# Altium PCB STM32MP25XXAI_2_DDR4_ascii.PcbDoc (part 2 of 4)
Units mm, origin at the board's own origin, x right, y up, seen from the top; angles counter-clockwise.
Board outline 172 x 137 mm, 4 copper layers (Top Layer, Signal Layer 1, Signal Layer 2, Bottom Layer), stack 1.614 mm thick; 241 components, 153 nets, 1312 pads, 924 vias.
Unrouted connection lines stored in the file: 13.
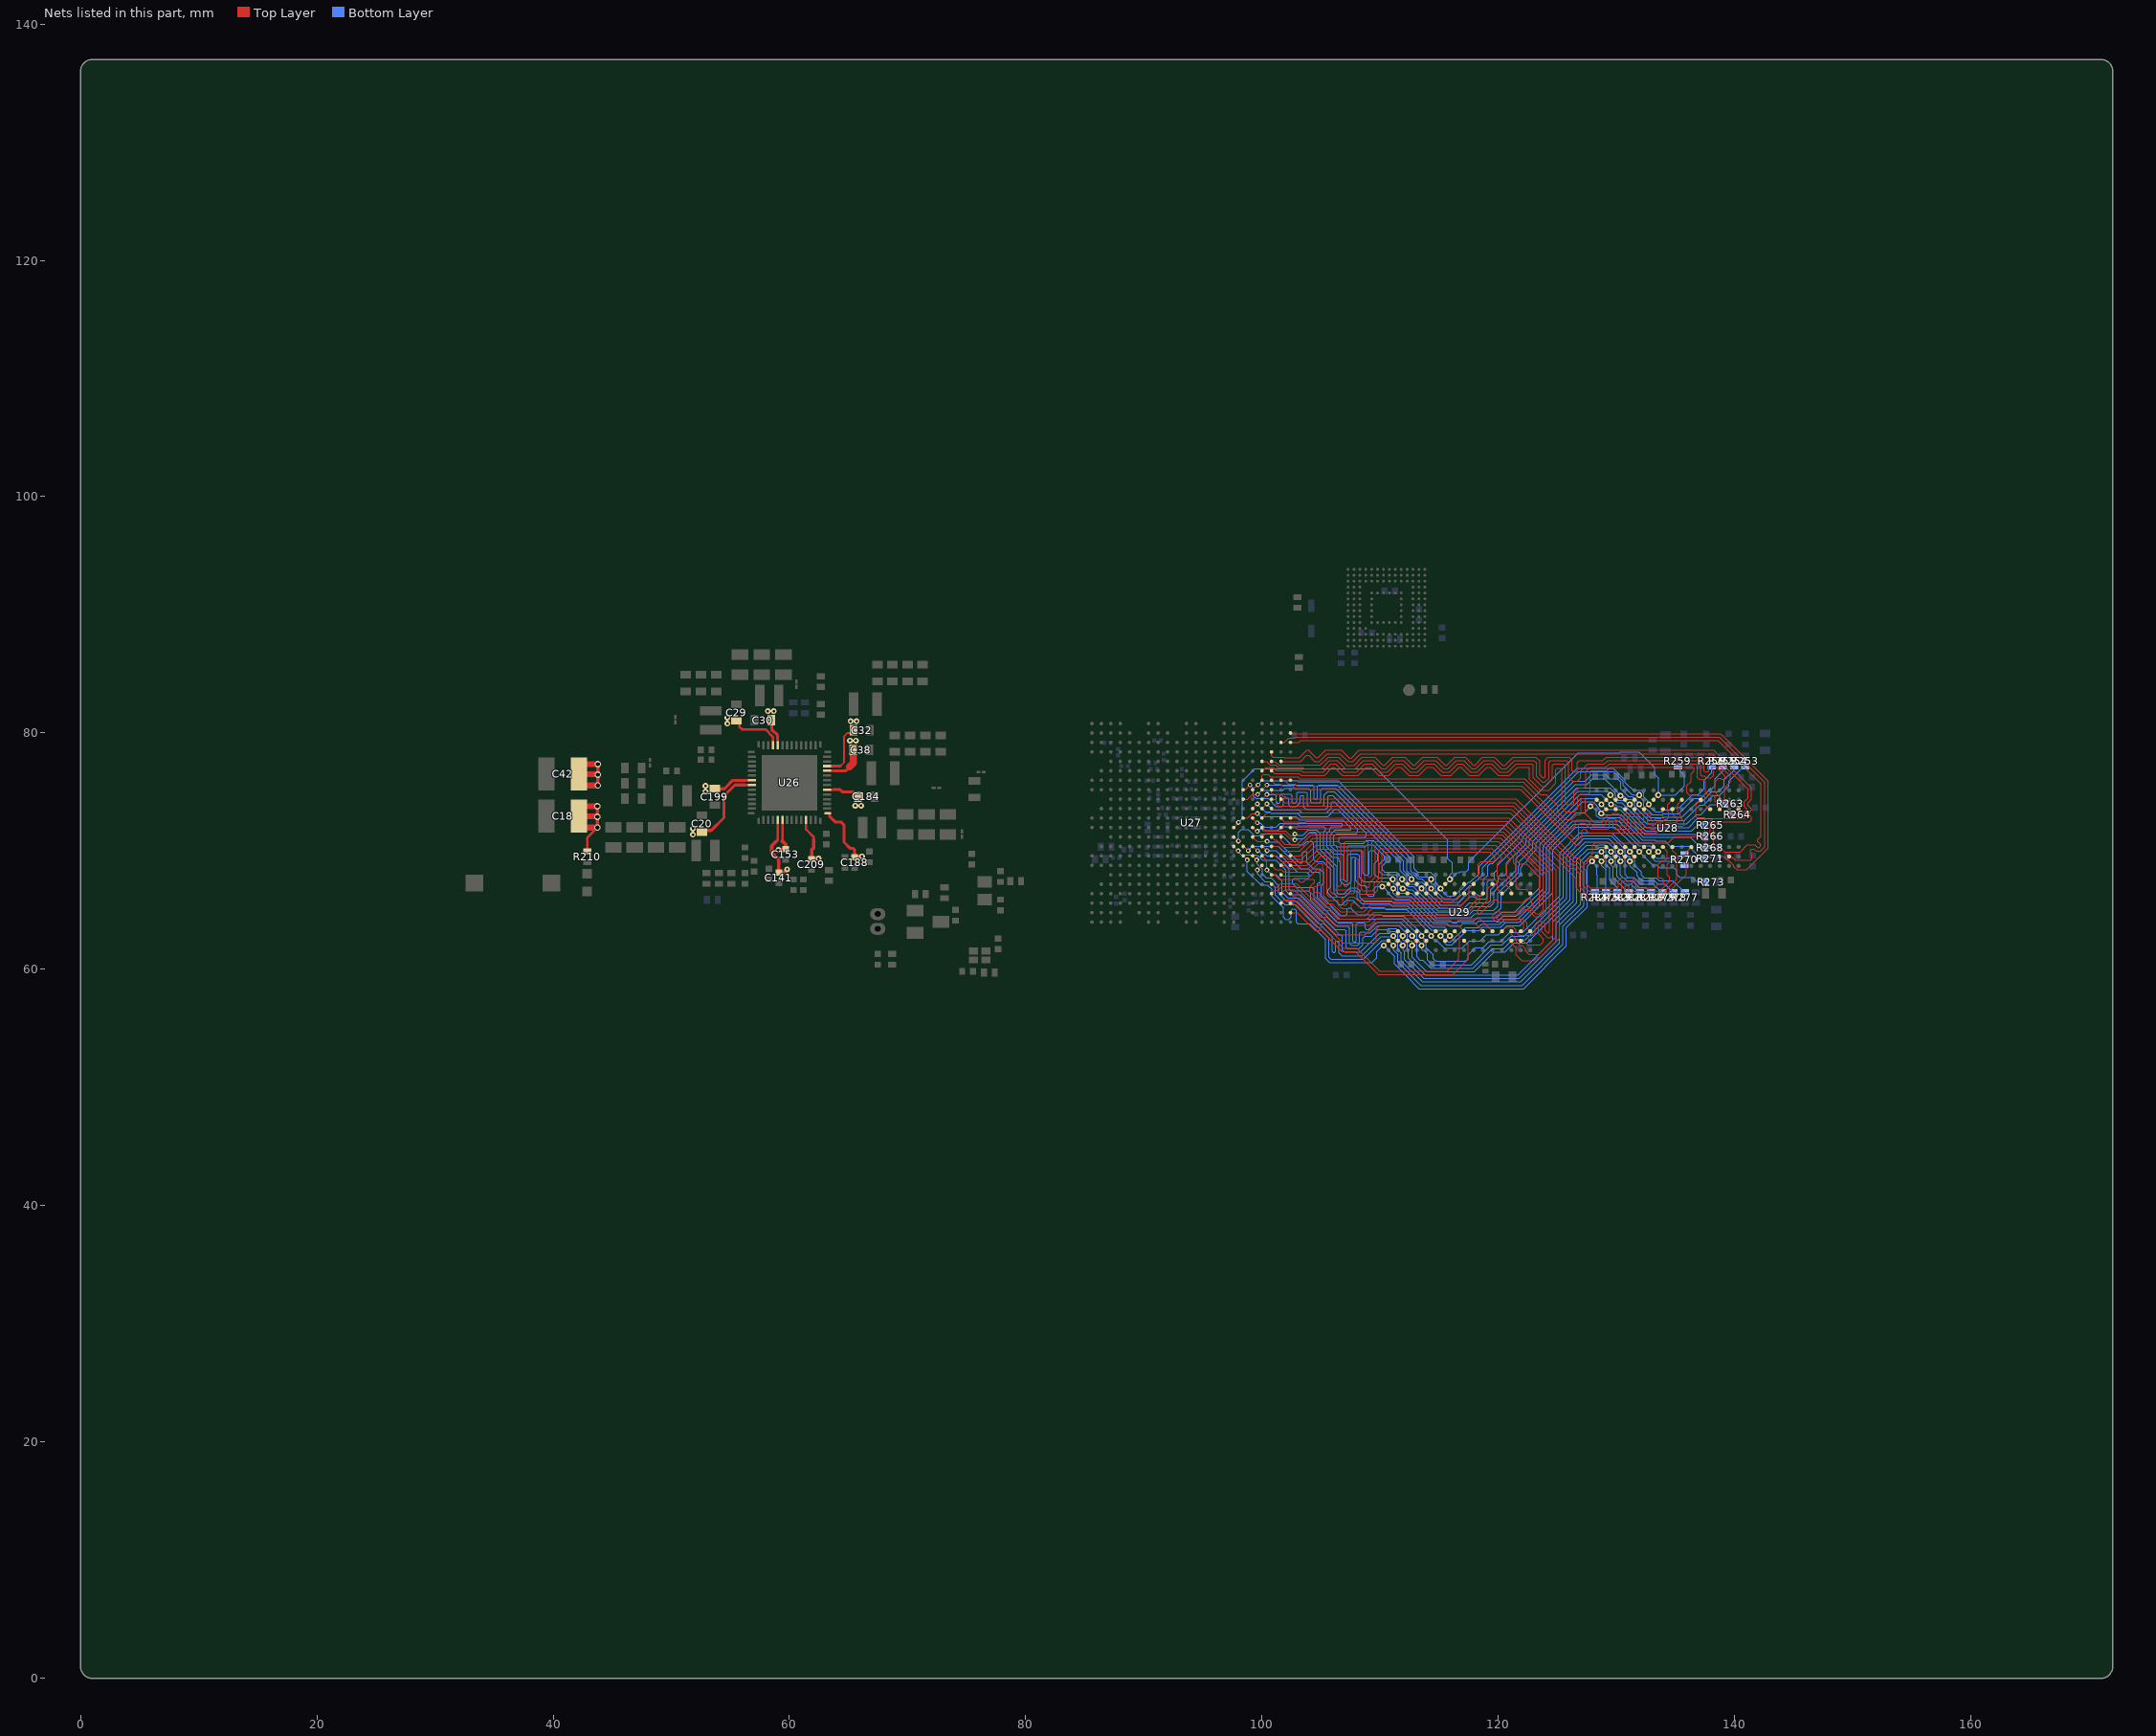
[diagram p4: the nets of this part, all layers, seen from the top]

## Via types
v1: diameter 0.55, hole 0.35, Top Layer to Bottom Layer, 432 vias
v2: diameter 0.4, hole 0.2, Top Layer to Bottom Layer, tented both sides, 202 vias
v3: diameter 0.5, hole 0.2, Top Layer to Bottom Layer, 146 vias
v4: diameter 0.5, hole 0.25, Top Layer to Bottom Layer, 144 vias

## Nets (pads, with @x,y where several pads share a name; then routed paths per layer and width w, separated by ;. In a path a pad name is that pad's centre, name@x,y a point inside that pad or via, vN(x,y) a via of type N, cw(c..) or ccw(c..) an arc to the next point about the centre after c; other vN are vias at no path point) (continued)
5V_STLK: C18.1 C20.2 C29.2 C30.2 C32.2 C38.2 C42.1 C153.2 C184.2 C188.2 C199.2 C209.2 R210.1 U26.6 U26.11 U26.15 U26.20 U26.24 U26.25 U26.38 U26.39 U26.49 U26.50 | length 56.5
  Top Layer w0.15: 64.3,77.2 64.625,77.525 64.625,79.731 64.888,79.994 65.319,79.994 C32.2@65.425,80.1
  Top Layer w0.2: R210.1@42.887,69.97 42.887,71.138 v1(43.751,72.002)
  Top Layer w0.21: C29.2@55.525,81.05 55.762,80.813 55.762,80.513 55.975,80.3 57.964,80.3 58.6,79.664 U26.39@58.6,78.97 ; 56.275,75.6 U26.50@56.83,75.6 ; 56.275,76 U26.49@56.83,76 ; U26.38@59,78.97 59,79.525 ; 59.4,70.85 U26.6@59.4,72.63 ; U26.11@61.4,72.63 61.4,71.843 62.04,71.203 62.04,70.975 ; U26.15@63.17,73.2 U26.15@63.245,73.2 U26.15@63.285,73.2 ; U26.20@63.17,75.2 63.725,75.2 ; U26.24@63.17,76.8 63.725,76.8 ; U26.25@63.17,77.2 64.3,77.2
  Top Layer w0.25: C20.2@52.6,71.75 53.375,71.75 54.45,72.825 54.45,74.669 55.381,75.6 56.275,75.6 ; C199.2@53.675,75.275 54.491,75.275 55.216,76 56.275,76 ; C30.2@58.425,81.075 58.494,81.006 58.494,80.308 59,79.802 59,79.525 ; 63.395,73.095 63.395,72.947 63.871,72.472 64.353,72.472 64.625,72.2 64.625,70.759 65.134,70.25 65.379,70.25 65.525,70.104 C188.2@65.525,69.55 ; 63.725,75.2 64.288,75.2 64.463,75.025 65.347,75.025 65.472,74.9 65.55,74.9 65.747,74.703 C184.2@65.747,74.625 ; 63.725,76.8 64.75,76.8 65.075,77.125
  Top Layer w0.3: v1(43.751,72.002) v1(43.751,72.902) v1(43.751,73.802) ; v1(43.776,75.565) v1(43.776,76.465) v1(43.776,77.365) ; v3(59.065,70.11) 59.675,70.11 59.674,70.111 59.674,70.576 59.4,70.85 ; C209.2@61.85,69.38 C209.2@61.875,69.38 ; 62.04,70.975 62.04,70.269 61.875,70.104 C209.2@61.875,69.38 ; v3(62.46,69.38) C209.2@61.875,69.38 ; C188.2@65.525,69.55 v3(66.135,69.55)
  Top Layer w0.5: C18.1@42.187,72.049 42.235,72.002 v1(43.751,72.002) ; C18.1@42.187,72.961 43.679,72.961 43.737,72.902 v1(43.751,72.902) ; C42.1@42.187,75.612 42.235,75.565 v1(43.776,75.565) ; C42.1@42.187,76.523 43.704,76.523 43.762,76.465 v1(43.776,76.465) ; C18.1@42.246,73.802 v1(43.751,73.802) ; C42.1@42.246,77.365 v1(43.776,77.365)
  Top Layer w0.6: 65.075,77.125 65.4,77.45 C38.2@65.4,78.175
  other v3: 51.825,71.4 51.825,71.9 65.575,73.85 66.075,73.85 52.9,75.025 52.9,75.525 65.125,79.35 65.625,79.35 54.75,80.8 65.175,81 65.675,81 54.75,81.3 58.175,81.85 58.675,81.85
5V_VCONN: C141.1 U26.5 | length 5.7
  Top Layer w0.21: 58.877,70.828 59,70.95 U26.5@59,72.63
  Top Layer w0.3: 58.877,70.828 58.51,70.46 58.51,69.865 59.1,69.275 C141.1@59.1,68.2 59.539,68.2 v3(59.8,68.46)
DDR_A0: R265.1 U27.K18 U28.P3 U29.P3 | length 57.5
  Top Layer w0.09: U27.K18@99.2,73.6 v2(99.6,74) ; v4(111.9,66.825) 111.941,66.825 112.294,66.472 U29.P3@112.294,66.422 ; v4@129.532,73.928 129.572,73.928 129.925,73.575 U28.P3@129.925,73.55 U28.P3@129.925,73.525
  Bottom Layer w0.09: v2(99.6,74) 100.267,73.333 100.646,73.333 100.771,73.209 102.988,73.209 103.252,72.945 105.581,72.945 106.158,73.522 106.2,73.522 106.384,73.522 108.091,71.815 108.091,71.615 107.965,71.49 106.3,71.49 106.077,71.267 106.077,70.58 106.3,70.357 108.748,70.357 ; 108.748,70.359 108.914,70.526 109.38,70.526 110.359,69.547 110.359,69.324 109.909,68.874 109.909,68.291 110.177,68.022 111.269,68.022 111.449,67.842 111.449,67.352 111.894,66.908 v4@111.938,66.863 ; v4(111.9,66.825) 111.938,66.862 112.233,66.862 112.365,66.73 112.708,66.73 114.805,64.633 117.533,64.633 117.9,65 119.589,65 119.939,65.349 119.939,66.445 121.7,68.206 121.7,68.718 121.76,68.779 121.76,69.109 122.92,70.269 122.92,70.811 126.885,74.775 128.71,74.775 129.525,73.959 v4(129.525,73.95) ; v4@129.551,73.95 129.885,73.95 130.04,73.795 130.363,73.795 132.433,71.725 136.35,71.725 136.825,72.2 R265.1@137.5,72.2
DDR_A1: R281.1 U27.P16 U28.P7 U29.P7 | length 54.7
  Top Layer w0.09: U27.P16@97.6,70.4 v2(97.975,70.025) ; v4(111.9,62.825) U29.P7@112.3,63.225 ; v4@129.54,69.936 U28.P7@129.932,70.328
  Bottom Layer w0.09: v2(97.975,70.025) 97.975,69.95 98.25,69.675 99.45,69.675 99.53,69.595 99.693,69.595 100.029,69.259 101.146,69.259 101.995,68.41 101.995,66.636 102.285,66.347 103.212,66.347 106.181,63.378 106.972,63.378 107.099,63.25 107.099,61.878 107.235,61.742 108.219,61.742 108.555,62.078 108.555,62.657 108.702,62.804 109.281,62.804 109.834,63.357 110.575,63.357 110.675,63.457 111.319,63.457 111.37,63.405 111.9,62.875 v4(111.9,62.825) ; v4@111.9,62.816 111.9,62.504 111.985,62.42 112.064,62.42 112.295,62.189 112.295,61.694 112.365,61.624 112.365,60.958 113.803,59.52 121.655,59.52 124.605,62.47 124.605,64 126.361,65.756 126.361,69.387 127.456,70.482 128.43,70.482 128.483,70.535 129.004,70.535 129.525,70.014 v4(129.525,69.95) 129.525,69.9 129.725,69.7 129.725,69.509 129.92,69.314 129.92,68.88 130.035,68.765 130.035,67.886 130.722,67.2 131.225,67.2 131.9,66.525 R281.1@131.975,66.525
DDR_A2: R268.1 U27.L18 U28.R3 U29.R3 | length 60.6
  Top Layer w0.09: U27.L18@99.2,72.8 v2(99.6,72.4) ; v4(111.1,66.825) 111.141,66.825 111.494,66.472 U29.R3@111.494,66.422 ; v4(128.703,73.185) 128.781,73.263 128.781,73.381 128.908,73.508 129.084,73.508 U28.R3@129.125,73.55
  Bottom Layer w0.09: v2(99.6,72.4) 99.622,72.378 99.872,72.378 100.195,72.055 101.218,72.055 101.528,72.365 106.721,72.365 106.794,72.291 106.794,72.149 106.716,72.07 105.894,72.07 105.758,71.934 105.758,71.768 105.497,71.508 105.497,70.339 106.06,69.777 106.75,69.777 106.925,69.602 106.925,67.578 107.028,67.475 107.168,67.475 107.254,67.56 107.254,69.636 107.395,69.777 108.048,69.777 108.235,69.59 108.235,67.779 108.578,67.437 110.489,67.437 v4(111.1,66.825) 111.103,66.823 111.103,66.466 111.409,66.16 112.571,66.16 114.598,64.133 115.925,64.133 ; 115.925,64.132 116.116,63.94 116.457,63.94 116.65,64.133 117.958,64.133 118.21,64.385 ; 118.212,64.385 118.227,64.401 119.865,64.401 120.277,64.813 121.373,64.813 123.5,66.94 123.5,70.57 127.125,74.195 127.964,74.195 128.055,74.104 128.277,73.882 128.277,73.84 128.635,73.482 128.635,73.253 v4(128.703,73.185) 128.778,73.109 130.37,73.109 132.282,71.197 ; 132.28,71.195 136.23,71.195 137.125,70.3 R268.1@137.5,70.3
DDR_A3: R279.1 U27.P19 U28.N7 U29.N7 | length 57
  Top Layer w0.09: U27.P19@100,70.4 100.038,70.4 100.388,70.05 v2(100.425,70.05) ; v4(112.7,62.825) 112.724,62.825 113.094,63.195 U29.N7@113.094,63.222 ; v4@130.355,69.928 130.725,70.298 U28.N7@130.725,70.325
  Bottom Layer w0.09: v2(100.425,70.05) 101.175,70.05 102.992,68.234 103.762,68.234 103.993,68.003 103.993,67.765 103.94,67.713 102.738,67.713 102.575,67.55 102.575,67.25 102.898,66.927 104.298,66.927 104.415,66.81 104.415,65.963 106.421,63.958 107.549,63.958 107.679,63.828 107.679,62.403 107.759,62.322 107.922,62.322 107.975,62.375 107.975,63.81 108.123,63.958 108.606,63.958 108.725,63.839 108.725,63.481 108.822,63.384 109.037,63.384 109.631,63.978 111.711,63.978 112.661,63.028 112.661,62.864 v4(112.7,62.825) 112.7,62.775 112.9,62.575 112.9,62.384 113.104,62.18 113.104,61.046 113.37,60.78 113.595,60.78 114.275,60.1 117.854,60.1 119.521,61.767 120.455,61.767 121.221,62.533 122.318,62.533 125.781,65.997 125.781,69.627 127.204,71.05 129.338,71.05 130.17,70.217 130.17,70.208 130.325,70.053 130.325,69.9 130.513,69.713 130.513,69.588 130.6,69.5 130.6,69.434 130.72,69.314 130.72,68.021 130.939,67.803 131.443,67.803 132.021,67.225 133.086,67.225 133.376,66.935 133.389,66.935 133.39,66.934 133.417,66.934 133.825,66.525 R279.1@133.875,66.525
  other v4: 130.325,69.95
DDR_A4: R263.1 U27.H17 U28.N3 U29.N3 | length 59.9
  Top Layer w0.09: U27.H17@98.4,75.2 98.419,75.219 98.604,75.219 v2@98.98,75.595 ; U29.N3@113.094,66.422 113.094,66.47 113.449,66.825 v4@113.5,66.825 ; U28.N3@130.725,73.525 130.725,73.573 131.102,73.95 v4(131.125,73.95)
  Bottom Layer w0.09: v2(98.98,75.6) 99.255,75.325 99.255,74.682 99.484,74.453 100.517,74.453 101.181,73.789 101.696,73.789 101.829,73.922 101.829,74.427 101.924,74.522 102.164,74.522 102.256,74.429 102.256,73.922 102.389,73.789 102.904,73.789 103.221,74.105 103.221,74.641 103.3,74.72 103.458,74.72 103.528,74.65 103.528,73.747 103.751,73.525 105.341,73.525 105.563,73.747 105.563,74.638 105.65,74.725 106.001,74.725 111.695,69.031 111.695,68.342 112.251,67.787 112.251,67.397 112.438,67.21 112.85,67.21 113.002,67.059 113.267,67.059 113.5,66.825 113.5,66.718 113.498,66.715 115.031,65.182 117.108,65.182 117.55,65.625 119.139,65.625 119.359,65.844 119.359,66.748 120.012,67.402 120.012,67.833 120.125,67.945 120.508,67.945 120.695,68.133 120.695,68.98 122.34,70.625 122.34,71.051 126.645,75.355 129.429,75.355 129.87,74.914 129.87,74.756 129.925,74.701 129.925,74.541 130.161,74.305 130.651,74.305 131.006,73.95 v4(131.125,73.95) 131.125,73.825 131.395,73.555 131.395,73.47 132.56,72.305 135.952,72.305 136.748,73.101 137.126,73.101 137.95,73.925 R263.1@139.2,73.925
  other v4: 113.5,66.85
DDR_A5: R282.1 U27.R19 U28.P8 U29.P8 | length 50.8
  Top Layer w0.09: U27.R19@100,69.6 100.4,69.2 v2(100.4,68.4) ; v4(111.9,62.025) 111.9,62.055 U29.P8@112.269,62.424 ; v4@129.532,69.158 U28.P8@129.901,69.527
  Bottom Layer w0.09: v2(100.4,68.4) 100.785,68.015 101.15,68.015 101.705,67.46 101.705,66.516 102.165,66.057 103.092,66.057 106.228,62.92 106.686,62.92 106.809,62.797 106.809,61.639 106.996,61.452 108.339,61.452 109.954,63.067 110.784,63.067 110.937,63.22 111.264,63.22 111.495,62.989 111.495,62.545 111.9,62.14 v4(111.9,62.025) 111.939,61.986 111.939,61.64 112.075,61.504 112.075,60.838 113.683,59.23 121.775,59.23 124.895,62.35 124.895,63.88 126.651,65.636 126.651,69.267 127.574,70.189 128.406,70.189 128.562,70.345 128.889,70.345 129.12,70.114 129.12,69.8 129.13,69.79 129.13,69.786 129.362,69.555 129.431,69.555 129.5,69.485 129.5,69.175 v4(129.525,69.15) 129.525,68.85 129.7,68.675 129.7,67.775 130.95,66.525 R282.1@131.025,66.525
DDR_A6: R264.1 U27.K19 U28.P2 U29.P2 | length 60.3
  Top Layer w0.09: U27.K19@100,73.6 v2(100.4,74) ; v4@111.9,67.6 111.916,67.6 112.283,67.233 U29.P2@112.308,67.233 ; v4(129.475,74.75) 129.5,74.75 129.9,74.35 U28.P2@129.925,74.35
  Bottom Layer w0.09: v2(100.4,74) 100.4,73.99 100.891,73.499 103.108,73.499 103.372,73.235 105.461,73.235 105.853,73.627 105.853,74.078 105.975,74.2 106.116,74.2 108.8,71.516 108.8,71.292 108.708,71.2 106.6,71.2 106.5,71.1 106.5,70.747 106.6,70.647 108.578,70.647 108.814,70.883 109.433,70.883 109.803,70.513 110.894,69.422 110.894,69.208 110.773,69.087 110.532,69.087 110.199,68.754 110.199,68.412 110.225,68.385 110.361,68.25 111.315,68.25 111.9,67.664 111.9,67.489 112.022,67.368 112.022,67.357 112.359,67.02 112.772,67.02 114.86,64.932 117.283,64.932 117.675,65.325 119.326,65.325 119.649,65.648 119.649,66.565 121.495,68.411 121.495,69.37 122.63,70.505 122.63,70.931 126.765,75.065 129.21,75.065 v4@129.5,74.775 ; v4(129.475,74.75) 129.745,74.48 129.745,74.37 130.03,74.085 130.432,74.085 132.502,72.015 136.126,72.015 136.861,72.75 139.327,72.75 139.431,72.855 139.59,72.855 139.8,73.065 R264.1@139.8,73.075
  other v4: 111.85,67.625
DDR_A7: R275.1 U27.T19 U28.R8 U29.R8 | length 48.8
  Top Layer w0.09: v2(99.6,68.4) U27.T19@100,68.8 ; v4(111.1,62.025) U29.R8@111.5,62.425 ; v4@128.732,69.128 U28.R8@129.132,69.528
  Bottom Layer w0.09: v2(99.6,68.4) 99.607,68.393 99.607,68.059 100.231,67.435 100.628,67.435 101.125,66.938 101.125,66.276 101.924,65.477 102.823,65.477 105.649,62.65 105.649,61.035 105.812,60.872 108.587,60.872 ; 108.587,60.873 110.132,62.417 110.134,62.417 110.137,62.42 110.705,62.42 v4(111.1,62.025) ; v4@111.107,62.025 111.126,62.006 111.126,61.633 111.495,61.264 111.495,60.598 113.443,58.65 122.015,58.65 125.475,62.11 125.475,63.64 127.231,65.396 127.231,69.026 127.75,69.545 128.337,69.545 v4@128.725,69.157 ; v4@128.732,69.15 128.757,69.125 128.757,68.776 129.12,68.413 R275.1@129.12,66.53
  other v4: 128.725,69.15
DDR_A8: R266.1 U27.L17 U28.R2 U29.R2 | length 60.5
  Top Layer w0.09: U27.L17@98.4,72.8 98.783,72.8 99.158,73.175 v2(99.6,73.175) ; v4@111.094,67.622 U29.R2@111.494,67.222 ; v4(128.725,73.95) U28.R2@129.125,74.35
  Bottom Layer w0.09: v2(99.6,73.175) 99.856,72.919 102.868,72.919 103.132,72.655 106.841,72.655 107.525,71.971 107.525,71.833 107.473,71.78 106.18,71.78 105.787,71.388 105.787,70.46 106.18,70.067 108.458,70.067 108.525,70 108.525,68.156 108.694,67.988 108.975,67.988 109.075,68.088 109.075,69.967 109.175,70.067 109.429,70.067 109.805,69.691 109.805,69.23 109.519,68.944 109.519,68.027 109.814,67.732 v4@110.873,67.732 ; v4@111.14,67.576 111.14,67.293 111.213,67.22 111.264,67.22 111.5,66.984 111.5,66.525 111.595,66.43 112.655,66.43 114.702,64.383 117.693,64.383 118.001,64.691 119.716,64.691 120.229,65.203 120.229,66.303 121.905,67.98 121.905,68.589 122.038,68.721 122.038,68.788 122.55,69.3 122.55,69.465 123.21,70.125 123.21,70.69 126.797,74.277 127.005,74.485 128.201,74.485 128.725,73.961 v4(128.725,73.95) 129.12,73.555 130.263,73.555 132.372,71.446 136.654,71.446 136.85,71.25 R266.1@137.5,71.25
  other v4: 111.05,67.625
DDR_A9: R283.1 U27.R18 U28.R7 U29.R7 | length 52.1
  Top Layer w0.09: U27.R18@99.2,69.6 v2(99.55,69.25) ; v4(111.1,62.825) 111.494,63.218 U29.R7@111.494,63.222 ; v4@128.732,69.928 129.125,70.321 U28.R7@129.125,70.325
  Bottom Layer w0.09: v2(99.55,69.25) 99.595,69.205 99.595,68.9 100.026,68.47 100.026,68.05 100.346,67.73 100.66,67.73 100.665,67.725 100.749,67.725 101.415,67.058 101.415,66.396 102.044,65.767 102.943,65.767 105.939,62.77 105.939,61.528 106.021,61.446 106.135,61.446 106.229,61.54 106.229,62.327 106.282,62.379 106.451,62.379 106.519,62.311 106.519,61.381 106.738,61.162 108.459,61.162 110.074,62.777 111.052,62.777 v4(111.1,62.825) 111.1,62.726 111.303,62.523 111.303,62.415 111.5,62.218 111.5,61.669 111.785,61.384 111.785,60.718 113.563,58.94 121.895,58.94 125.185,62.23 125.185,63.76 126.941,65.516 126.941,69.146 127.694,69.899 128.674,69.899 v4(128.725,69.95) ; v4@128.725,69.925 128.725,69.867 128.9,69.692 128.9,69.534 129.12,69.314 129.12,68.83 129.41,68.54 129.41,67.562 130.075,66.897 R283.1@130.075,66.525
DDR_A10: R254.1 U27.J17 U28.M3 U29.M3 | length 60
  Top Layer w0.09: U27.J17@98.4,74.4 98.783,74.4 99.183,74.8 v2(99.625,74.8) ; U29.M3@113.894,66.422 113.894,66.47 114.249,66.825 v4(114.3,66.825) ; U28.M3@131.525,73.55 131.525,73.573 v4@131.88,73.928
  Bottom Layer w0.09: v2(99.625,74.8) 99.632,74.8 99.977,75.145 101.792,75.145 101.948,75.3 103.933,75.3 104.108,75.125 104.108,74.2 104.204,74.105 104.886,74.105 104.983,74.203 104.983,75.2 105.088,75.305 106.242,75.305 112.275,69.271 112.275,68.325 112.58,68.02 112.814,68.02 113.187,67.647 113.531,67.647 114.091,67.087 114.091,67.083 114.3,66.873 v4(114.3,66.825) v4@114.3,66.717 ; v4@114.298,66.715 115.331,65.682 116.653,65.682 117.549,66.578 117.95,66.578 118.285,66.242 118.651,66.242 118.755,66.347 118.755,67.616 119.1,67.961 119.1,68.745 119.325,68.97 119.509,68.97 121.76,71.221 121.76,71.291 126.404,75.935 127.368,75.935 127.868,76.435 129.115,76.435 129.438,76.112 130.095,76.112 130.36,75.847 130.36,75.268 131.015,74.613 131.337,74.613 131.925,74.025 v4(131.925,73.95) 131.925,73.836 132.22,73.541 132.22,73.466 132.851,72.835 133.987,72.835 134.037,72.885 135.554,72.885 136.864,74.195 137.255,74.195 138.075,75.015 138.599,75.015 139.12,75.536 139.12,76.034 139.95,76.864 R254.1@139.95,77.175
DDR_A11: R271.1 U27.M18 U28.T2 U29.T2 | length 59.8
  Top Layer w0.09: U27.M18@99.2,72 99.237,72 99.562,71.675 v2(99.6,71.675) ; v4(110.175,67) 110.423,67 110.647,67.224 U29.T2@110.694,67.224 ; v4@127.797,73.798 U28.T2@128.326,74.327
  Bottom Layer w0.09: v2(99.6,71.675) 99.6,71.677 99.79,71.867 99.973,71.867 100.089,71.751 101.324,71.751 101.648,72.075 105.226,72.075 105.375,71.925 105.375,71.796 105.207,71.628 105.207,70.219 105.94,69.487 106.405,69.487 106.52,69.372 106.52,69.168 106.635,69.053 106.635,67.458 106.908,67.185 107.288,67.185 107.579,67.475 107.579,69.402 107.664,69.487 107.858,69.487 107.945,69.4 107.945,67.505 108.35,67.1 108.75,67.1 108.855,66.995 108.855,66.376 109.015,66.215 109.412,66.215 109.519,66.322 109.519,66.856 109.662,67 v4(110.175,67) 110.216,67 110.625,66.59 110.625,66.507 111.242,65.89 112.488,65.89 114.495,63.883 115.625,63.883 115.858,63.65 116.782,63.65 117.015,63.883 118.118,63.883 118.33,64.095 ; 118.332,64.095 118.347,64.111 119.985,64.111 120.397,64.523 121.493,64.523 123.79,66.82 123.79,70.45 126.59,73.25 127.266,73.25 127.8,73.784 v4(127.8,73.8) 127.907,73.8 128.301,73.406 128.301,73.028 128.539,72.79 128.866,72.79 128.919,72.842 130.297,72.842 132.18,70.959 133.217,70.959 133.327,70.85 134.1,70.85 134.545,70.405 136.12,70.405 137.175,69.35 R271.1@137.5,69.35
DDR_A12: R277.1 U27.N18 U28.M7 U29.M7 | length 56.3
  Top Layer w0.09: U27.N18@99.2,71.2 99.575,70.825 v2(100.425,70.825) ; v4(113.5,62.825) 113.524,62.825 113.894,63.195 U29.M7@113.894,63.222 ; v4@131.132,69.928 131.155,69.928 131.525,70.298 U28.M7@131.525,70.325
  Bottom Layer w0.09: v2(100.425,70.825) 100.45,70.8 101.386,70.8 103.202,68.984 103.334,68.984 103.438,69.087 103.438,69.885 103.525,69.973 103.7,69.973 103.791,69.882 103.791,69.046 104.31,68.528 104.9,68.528 105.225,68.202 105.225,67.308 104.995,67.078 104.995,66.204 106.661,64.538 107.038,64.538 107.19,64.69 107.19,65.07 107.327,65.206 107.474,65.206 108.035,64.645 110.092,64.645 110.217,64.52 111.99,64.52 113.422,63.088 113.422,62.903 v4(113.5,62.825) 113.711,62.614 113.711,62.373 113.895,62.189 113.895,61.84 114.505,61.23 114.505,60.911 114.737,60.68 117.214,60.68 117.45,60.916 117.45,61.234 118.042,61.825 118.704,61.825 119.227,62.348 120.216,62.348 120.981,63.113 122.077,63.113 125.2,66.236 125.2,69.866 126.884,71.55 129.608,71.55 131.125,70.033 v4(131.125,69.95) 131.35,69.725 131.35,69.556 131.522,69.385 131.522,68.795 132.105,68.211 132.105,67.986 132.337,67.755 133.377,67.755 133.617,67.515 133.629,67.515 133.63,67.514 134.746,67.514 135.735,66.525 R277.1@135.775,66.525
DDR_A13: R284.1 U27.R17 U28.T8 U29.T8 | length 51.4
  Top Layer w0.09: U27.R17@98.4,69.6 v2(98.75,69.25) ; v4(110.3,62.025) 110.3,62.055 U29.T8@110.669,62.424 ; v4@127.932,69.158 128.004,69.23 128.255,69.481 U28.T8@128.301,69.527
  Bottom Layer w0.09: v2(98.75,69.25) 98.75,68.29 99.895,67.145 100.456,67.145 100.835,66.765 100.835,66.156 101.804,65.187 101.804,64.422 101.985,64.242 102.274,64.242 102.453,64.42 102.453,64.976 102.602,65.125 102.764,65.125 102.907,64.982 102.907,63.977 103.017,63.867 104.022,63.867 105.359,62.53 105.359,60.908 105.685,60.582 109.315,60.582 109.698,60.965 109.698,61.503 110.22,62.025 v4(110.3,62.025) 111.204,61.121 111.204,60.438 112.167,59.475 113.282,58.36 122.135,58.36 125.765,61.99 125.765,63.52 127.521,65.276 127.521,68.734 127.925,69.138 v4(127.925,69.15) ; v4@127.925,69.125 128.323,68.728 128.323,67.936 128.375,67.884 128.375,66.725 R284.1@128.175,66.525
DDR_ACTN: R256.1 U27.H18 U28.L3 U29.L3 | length 54.5
  Top Layer w0.09: U27.H18@99.2,75.2 99.6,75.6 v2(99.65,75.6) ; U29.L3@114.694,66.422 114.694,66.47 115.049,66.825 v4(115.1,66.825) ; U28.L3@132.325,73.525 132.325,73.573 v4@132.68,73.928
  Bottom Layer w0.09: v2@99.658,75.6 100.003,75.945 106.422,75.945 112.855,69.511 112.855,68.531 113.136,68.25 114.234,68.25 114.695,67.789 114.695,67.291 115.1,66.886 115.1,66.755 115.656,66.2 116.288,66.2 117.473,67.385 117.624,67.385 118.362,68.123 118.362,68.484 118.362,68.713 126.664,77.015 129.73,77.015 130.74,76.005 130.74,75.805 131.4,75.145 132.089,75.145 132.09,75.144 132.325,74.909 132.325,74.582 132.647,74.26 132.647,74.028 v4(132.725,73.95) 132.725,73.852 133.262,73.315 133.788,73.315 133.948,73.475 134.475,73.475 134.703,73.703 135.361,73.703 136.433,74.775 136.919,74.775 137.425,75.281 137.425,76.024 138.05,76.65 R256.1@138.05,77.175
DDR_BA0: R253.1 U27.J19 U28.N2 U29.N2 | length 61.5
  Top Layer w0.09: U27.J19@100,74.4 v2(100.4,74.8) ; v4@112.644,67.628 112.697,67.628 113.094,67.231 U29.N2@113.094,67.222 ; v4(130.325,74.7) 130.371,74.7 130.698,74.373 U28.N2@130.725,74.373
  Bottom Layer w0.09: v2(100.4,74.8) 100.409,74.791 101.065,74.791 101.199,74.657 101.199,74.173 101.294,74.079 101.445,74.079 101.539,74.173 101.539,74.696 101.666,74.824 102.412,74.824 102.546,74.689 102.546,74.174 102.642,74.079 102.784,74.079 102.931,74.225 102.931,74.91 103.031,75.01 103.725,75.01 103.818,74.917 103.818,73.94 103.943,73.815 105.166,73.815 105.273,73.922 105.273,74.758 105.53,75.015 106.121,75.015 111.985,69.151 111.985,68.346 112.65,67.682 v4(112.65,67.625) 112.67,67.625 112.895,67.4 113.509,67.4 113.901,67.008 113.901,66.666 115.135,65.432 116.862,65.432 117.603,66.172 117.948,66.172 118.168,65.952 118.931,65.952 119.069,66.09 119.069,67.39 119.203,67.524 119.548,67.524 119.686,67.662 119.686,68.202 119.905,68.421 119.905,68.81 122.05,70.955 122.05,71.171 126.524,75.645 127.488,75.645 127.988,76.145 128.939,76.145 129.129,75.955 129.129,75.952 130.325,74.756 v4(130.325,74.7) 130.387,74.638 130.633,74.638 130.904,74.367 131.267,74.367 131.52,74.114 131.52,73.78 132.705,72.595 135.744,72.595 137.054,73.905 137.376,73.905 138.196,74.725 138.719,74.725 139.512,75.518 139.512,75.933 140.15,76.572 140.15,76.59 140.235,76.675 140.299,76.675 140.799,77.175 R253.1@140.9,77.175
DDR_BA1: R280.1 U27.P18 U28.N8 U29.N8 | length 53.8
  Top Layer w0.09: U27.P18@99.2,70.4 99.237,70.4 99.588,70.05 v2(99.625,70.05) ; v4(112.7,62.025) 112.7,62.055 U29.N8@113.069,62.424 ; v4@130.332,69.158 U28.N8@130.701,69.527
  Bottom Layer w0.09: v2(99.625,70.05) 99.648,70.05 99.974,69.724 100.264,69.724 100.38,69.607 101.208,69.607 102.285,68.53 102.285,66.756 102.405,66.637 103.928,66.637 104.125,66.44 104.125,65.843 106.301,63.668 107.22,63.668 107.389,63.499 107.389,62.214 107.571,62.032 108.099,62.032 108.265,62.198 108.265,63.04 108.375,63.15 108.646,63.15 108.702,63.094 109.157,63.094 109.771,63.708 111.576,63.708 112.299,62.985 112.299,62.531 112.428,62.402 112.613,62.402 112.7,62.315 v4(112.7,62.025) 112.7,61.033 113.924,59.81 117.974,59.81 119.641,61.477 120.575,61.477 121.341,62.243 122.438,62.243 126.071,65.876 126.071,69.507 127.365,70.8 129.234,70.8 129.92,70.114 129.92,69.796 130.162,69.555 130.245,69.555 130.3,69.5 130.3,69.175 v4(130.325,69.15) 130.325,68.006 130.832,67.5 131.335,67.5 131.9,66.935 132.44,66.935 132.85,66.525 R280.1@132.925,66.525
DDR_BG0: R255.1 U27.H19 U28.M2 U29.M2 | length 56.7
  Top Layer w0.09: U27.H19@100,75.2 v2(100.4,75.6) ; U29.M2@113.894,67.222 113.894,67.27 114.249,67.625 v4(114.3,67.625) ; U28.M2@131.525,74.325 131.525,74.373 v4@131.88,74.728
  Bottom Layer w0.09: v2(100.4,75.6) 104.298,75.6 104.398,75.5 104.398,74.479 104.482,74.395 104.612,74.395 104.693,74.476 104.693,75.468 104.825,75.6 106.357,75.6 112.565,69.391 112.565,68.304 112.659,68.21 112.892,68.21 113.263,67.84 114.045,67.84 114.26,67.625 v4(114.3,67.625) 114.3,67.306 114.387,67.22 114.464,67.22 114.7,66.984 114.7,66.666 115.435,65.932 116.463,65.932 117.626,67.095 117.744,67.095 118.652,68.003 118.652,68.152 118.652,68.593 126.784,76.725 129.751,76.725 130.55,75.926 130.55,75.558 131.304,74.803 131.416,74.803 131.469,74.75 v4(131.925,74.75) 131.925,74.647 132.32,74.252 132.32,73.786 132.317,73.783 133.025,73.075 133.888,73.075 133.988,73.175 135.244,73.175 136.554,74.485 137.135,74.485 137.955,75.305 138.089,75.305 138.32,75.536 138.32,76.107 139,76.787 R255.1@139,77.175
DDR_CASN: R278.1 U27.P17 U28.M8 U29.M8 | length 53.7
  Top Layer w0.09: U27.P17@98.4,70.4 98.45,70.4 98.8,70.05 v2@98.85,70.05 ; v4(113.5,62.025) 113.5,62.055 U29.M8@113.869,62.424 ; v4@131.132,69.158 U28.M8@131.501,69.527
  Bottom Layer w0.09: v2@98.85,70.05 99.2,70.4 101.376,70.4 103.252,68.524 103.904,68.524 104.19,68.238 104.78,68.238 104.935,68.082 104.935,67.439 104.705,67.209 104.705,66.084 106.541,64.248 111.852,64.248 113.095,63.004 113.095,62.557 v4@113.441,62.211 ; v4@113.449,62.203 v4@113.441,62.211 ; R278.1@134.825,66.525 134.788,66.525 134.089,67.224 133.51,67.224 133.509,67.225 133.497,67.225 133.207,67.515 132.141,67.515 131.753,67.903 131.725,67.93 131.725,68.175 131.125,68.775 v4(131.125,69.15) 131.132,69.156 131.132,69.506 131.083,69.555 130.962,69.555 130.73,69.786 130.73,69.795 130.72,69.805 130.72,70.134 129.554,71.3 127.044,71.3 125.49,69.746 125.49,66.116 122.198,62.823 121.101,62.823 120.335,62.057 119.401,62.057 117.734,60.39 114.395,60.39 113.997,60.789 113.997,61.287 113.664,61.62 113.555,61.62 113.5,61.675 v4(113.5,62.025) 113.441,62.084 v4@113.441,62.211
  other v2: 98.825,70.05
DDR_CKE: R259.1 U27.M16 U28.K2 U29.K2 | length 58.7
  Top Layer w0.09: U27.M16@97.6,72 97.6,72.012 98,72.413 v2(98,72.425) ; U29.K2@115.5,67.225 v4(115.9,67.625) ; U28.K2@133.132,74.357 v4(133.525,74.75)
  Bottom Layer w0.09: v2(98,72.425) 98.345,72.77 98.345,75.92 99.386,76.961 109.669,76.961 115.684,70.946 ; 115.703,70.946 115.703,69.383 116.097,68.989 116.097,68.187 115.9,67.99 v4(115.9,67.625) 115.975,67.625 116.53,68.18 116.722,68.18 116.797,68.255 117.264,68.255 117.495,68.486 117.495,69.076 126.742,78.323 130.263,78.323 130.335,78.395 131.91,78.395 133.244,77.061 133.244,76.471 133.546,76.169 133.546,74.771 v4(133.525,74.75) 134.965,74.75 135.75,75.535 135.75,76.4 135.375,76.775 135.375,77 R259.1@135.2,77.175
DDR_CLK_N: R270.2 U27.M19 U28.K8 U29.K8 | length 53.6
  Top Layer w0.09: U27.M19@100,72 100.295,71.705 101.964,71.705 102.369,71.3 102.625,71.3 v2(102.775,71.45) ; U29.K8@115.494,62.422 115.494,62.472 115.847,62.825 v4(115.9,62.825) ; U28.K8@133.125,69.525 U28.K8@133.125,69.55 133.125,69.575 133.478,69.928 v4@133.532,69.928
  Bottom Layer w0.09: v2(102.775,71.45) 102.859,71.45 102.981,71.328 103.454,71.328 103.91,71.785 104.607,71.785 104.917,71.475 104.917,70.099 106.345,68.671 106.345,66.508 106.489,66.365 106.9,66.365 107.435,66.9 108.025,66.9 108.287,66.638 108.287,66.089 108.563,65.813 110.909,65.813 111.122,65.6 112.403,65.6 114.417,63.586 115.411,63.586 115.616,63.38 115.616,63.03 115.794,62.852 115.794,62.764 115.614,62.584 115.614,62.427 115.729,62.312 115.96,62.312 117.201,63.553 118.301,63.553 118.569,63.821 120.105,63.821 120.517,64.233 121.613,64.233 124.08,66.7 124.08,70.33 126.227,72.477 126.3,72.55 130.155,72.55 131.986,70.719 132.938,70.719 133.232,70.425 133.232,70.22 133.502,69.95 v4(133.525,69.95) 133.25,69.675 133.25,69.534 133.388,69.396 135.392,69.396 135.721,69.725 R270.2@135.75,69.725
DDR_CLK_P: R270.1 U27.N19 U28.K7 U29.K7 | length 53.5
  Top Layer w0.09: U27.N19@100,71.2 100.325,71.525 101.89,71.525 102.315,71.1 102.625,71.1 v2(102.775,70.95) ; v4(115.1,62.825) 115.147,62.825 115.494,63.172 U29.K7@115.494,63.222 ; v4@132.778,69.928 133.125,70.275 U28.K7@133.125,70.325
  Bottom Layer w0.09: v2(102.775,70.95) 102.855,70.95 102.983,71.078 103.557,71.078 104.014,71.535 104.504,71.535 104.667,71.371 104.667,69.996 106.095,68.568 106.095,66.405 106.385,66.115 107.004,66.115 107.539,66.65 107.921,66.65 108.037,66.535 108.037,65.985 108.459,65.563 110.806,65.563 111.018,65.35 112.299,65.35 114.313,63.336 115.307,63.336 115.366,63.277 115.366,63.03 v4@115.194,62.857 ; v4(115.1,62.825) 115.127,62.825 115.364,62.589 115.364,62.324 115.625,62.062 116.063,62.062 117.304,63.303 118.404,63.303 118.672,63.571 120.209,63.571 120.621,63.983 121.717,63.983 124.33,66.596 124.33,70.227 126.404,72.3 130.051,72.3 131.882,70.469 132.834,70.469 132.982,70.321 132.982,70.206 v4(132.725,69.95) 133,69.675 133,69.43 133.285,69.146 135.382,69.146 135.703,68.825 R270.1@135.75,68.825
DDR_CSN: R273.1 U27.N16 U28.L7 U29.L7 | length 57.8
  Top Layer w0.09: U27.N16@97.6,71.2 97.625,71.2 97.975,70.85 v2(98,70.85) ; v4(114.3,62.825) 114.332,62.825 114.669,63.163 U29.L7@114.669,63.224 ; v4@131.963,69.928 132.301,70.266 U28.L7@132.301,70.327
  Bottom Layer w0.09: v2(98,70.85) 98,71.6 98.25,71.85 98.8,71.85 99.352,71.298 99.779,71.298 99.941,71.46 101.546,71.46 102.453,70.553 103.528,70.553 103.8,70.825 104.25,70.825 104.371,70.704 104.371,69.286 104.55,69.108 105.14,69.108 105.805,68.443 105.805,66.98 105.575,66.75 105.575,66.444 106.54,65.479 106.78,65.479 107.125,65.825 107.675,65.825 108.275,65.225 110.332,65.225 110.497,65.06 112.215,65.06 114.3,62.975 v4(114.3,62.825) 114.3,62.775 114.65,62.425 114.754,62.425 115.407,61.772 116.937,61.772 117.57,62.405 118.464,62.405 118.987,62.928 119.976,62.928 120.741,63.693 121.837,63.693 124.62,66.476 124.62,70.106 126.564,72.05 129.853,72.05 131.368,70.535 131.911,69.991 131.911,69.978 131.925,69.964 v4(131.925,69.95) 133.036,68.839 133.4,68.839 133.632,68.607 134.35,68.607 ; 134.35,68.606 134.853,68.606 135.095,68.364 135.095,68.046 135.337,67.805 136.42,67.805 136.85,67.375 R273.1@137.55,67.375
DDR_DQ0: U27.W22 U29.F7 | length 18.5
  Top Layer w0.09: U27.W22@102.4,66.4 102.615,66.185 102.82,66.185 104.862,64.144 105.339,64.144 106.556,62.927 108.753,62.927 109.836,64.01 117.908,64.01 U29.F7@118.682,63.237
DDR_DQ1: U27.Y21 U29.H7 | length 18.5
  Top Layer w0.09: U27.Y21@101.6,65.6 101.6,65.628 101.867,65.895 102.7,65.895 104.741,63.854 105.219,63.854 106.826,62.246 109.511,62.246 109.669,62.405 109.669,63.377 110.012,63.72 116.596,63.72 U29.H7@117.094,63.222
DDR_DQ2: U27.Y22 U29.J7 | length 19.6
  Top Layer w0.09: U27.Y22@102.4,65.6 102.419,65.581 102.604,65.581 104.621,63.564 105.098,63.564 106.884,61.778 108.022,61.778 109.953,59.847 115.648,59.847 116.651,60.851 116.651,61.417 116.695,61.461 116.695,62.82 U29.J7@116.294,63.222
DDR_DQ3: U27.AA22 U29.H8 | length 19.5
  Top Layer w0.09: U27.AA22@102.4,64.8 102.975,64.8 104.501,63.274 104.978,63.274 106.764,61.488 107.902,61.488 109.843,59.547 116.149,59.547 117.453,60.851 117.453,62.063 U29.H8@117.094,62.422
DDR_DQ4: U27.T21 U29.J3 | length 20
  Top Layer w0.09: U27.T21@101.6,68.8 101.942,68.8 102.237,68.505 103.899,68.505 104.992,69.599 105.381,69.599 105.501,69.478 105.501,66.319 105.686,66.134 106.676,66.134 106.835,65.974 106.835,65.53 106.934,65.432 107.071,65.432 107.232,65.593 107.232,65.957 107.413,66.137 107.785,66.137 108.072,65.85 108.382,65.85 108.536,66.003 115.875,66.003 U29.J3@116.294,66.422
DDR_DQ5: U27.T20 U29.H2 | length 22.2
  Top Layer w0.09: U27.T20@100.8,68.8 101.182,68.418 101.67,68.418 101.873,68.215 104.019,68.215 104.777,68.973 105.038,68.973 105.139,68.872 105.139,68.517 105.211,68.445 105.211,66.198 105.566,65.844 106.371,65.844 106.423,65.791 106.423,65.463 106.744,65.142 107.523,65.142 107.576,65.195 107.576,65.527 107.706,65.658 107.848,65.658 108.364,65.142 108.498,65.142 108.612,65.256 108.612,65.628 108.697,65.713 116.104,65.713 116.735,66.345 116.735,66.864 U29.H2@117.094,67.222
DDR_DQ6: U27.U21 U29.H3 | length 20.3
  Top Layer w0.09: U27.U21@101.604,68.004 101.682,67.925 104.139,67.925 104.682,68.468 104.778,68.468 104.921,68.325 104.921,67.221 104.7,67 104.463,67 104.315,66.852 104.315,66.684 104.462,66.537 104.773,66.537 104.888,66.422 104.888,66.111 105.446,65.554 105.923,65.554 106.624,64.852 108.618,64.852 109.189,65.423 116.482,65.423 117.094,66.035 U29.H3@117.094,66.422
DDR_DQ7: U27.U20 U29.G2 | length 21.4
  Top Layer w0.09: U27.U20@100.8,68 101.078,68 101.452,67.626 103.005,67.626 103.231,67.4 103.475,67.4 103.7,67.626 104.375,67.626 104.428,67.573 104.428,67.375 104.025,66.972 104.025,66.564 105.326,65.264 105.803,65.264 106.504,64.562 108.738,64.562 109.309,65.133 116.602,65.133 117.544,66.074 117.544,66.872 U29.G2@117.894,67.222
DDR_DQ8: U27.M21 U29.B8 | length 36
  Top Layer w0.09: U27.M21@101.6,72 101.903,72.303 102.947,72.303 103.083,72.168 103.776,72.168 103.826,72.217 120.651,72.217 124.615,68.253 124.615,62.892 124.4,62.676 124.174,62.676 123.679,63.171 123.679,63.692 123.59,63.78 123.468,63.78 123.384,63.696 123.384,62.988 123.795,62.577 123.795,62.32 123.55,62.075 122.461,62.075 122.151,62.386 121.93,62.386 U29.B8@121.894,62.422
DDR_DQ9: U27.M22 U29.D7 | length 34.8
  Top Layer w0.09: U27.M22@102.4,72 102.84,72 102.963,71.878 103.896,71.878 103.946,71.927 120.531,71.927 124.325,68.133 124.325,63.15 124.255,63.08 124.18,63.08 123.969,63.291 123.969,63.812 123.711,64.07 123.348,64.07 123.094,63.817 123.094,63.063 122.908,62.877 121.751,62.877 121.474,63.154 121.474,63.339 121.241,63.573 120.644,63.573 U29.D7@120.294,63.222
DDR_DQ10: U27.L21 U29.C7 | length 36.4
  Top Layer w0.09: U27.L21@101.6,72.8 101.9,72.5 103.16,72.5 103.203,72.458 103.656,72.458 103.706,72.507 120.771,72.507 124.905,68.373 124.905,62.771 123.411,61.277 122.596,61.277 122.321,61.552 122.321,61.708 122.007,62.022 121.806,62.022 121.521,62.307 121.521,62.523 121.094,62.951 U29.C7@121.094,63.222
DDR_DQ11: U27.L22 U29.C8 | length 36.5
  Top Layer w0.09: U27.L22@102.403,72.797 120.891,72.797 125.195,68.493 125.195,62.651 123.531,60.987 123.257,60.987 123.025,60.755 121.984,60.755 121.984,60.758 121.507,61.234 121.507,61.777 121.15,62.134 121.15,62.375 U29.C8@121.1,62.425
DDR_DQ12: U27.T22 U29.D3 | length 35.7
  Top Layer w0.09: U27.T22@102.4,68.8 103.783,68.8 104.872,69.889 105.737,69.889 105.791,69.835 105.791,66.585 105.949,66.427 107.716,66.427 107.827,66.538 107.827,69.263 107.91,69.347 108.01,69.347 108.123,69.233 108.123,66.54 108.296,66.367 109.46,66.367 109.78,66.687 109.78,67.164 110.164,67.547 110.164,69.788 110.313,69.937 119.279,69.937 119.719,69.497 119.719,69.239 119.587,69.108 118.533,69.108 118.305,68.88 118.305,67.858 118.541,67.622 119.665,67.622 119.924,67.363 119.924,66.792 U29.D3@120.294,66.422
DDR_DQ13: U27.R20 U29.C3 | length 37.4
  Top Layer w0.09: U27.R20@100.8,69.6 101.138,69.6 101.636,69.102 103.675,69.102 104.765,70.192 105.844,70.192 106.081,69.955 106.081,66.825 106.188,66.717 107.424,66.717 107.537,66.83 107.537,70.029 107.653,70.145 108.296,70.145 108.413,70.028 108.413,66.754 108.51,66.657 109.34,66.657 109.49,66.807 109.49,67.284 109.874,67.667 109.874,70.049 110.052,70.227 119.483,70.227 120.263,69.447 120.269,69.447 120.269,69.337 119.902,68.97 119.902,67.875 120.149,67.628 120.538,67.628 120.694,67.472 120.694,67.085 121.08,66.698 121.08,66.436 U29.C3@121.094,66.422
DDR_DQ14: U27.R21 U29.C2 | length 36.8
  Top Layer w0.09: U27.R21@101.6,69.6 101.893,69.6 102.189,69.304 103.346,69.304 104.56,70.517 106.284,70.517 106.371,70.431 106.371,67.089 106.453,67.007 106.566,67.007 106.661,67.102 106.661,67.233 106.737,67.309 106.852,67.309 106.957,67.204 106.957,67.082 107.031,67.007 107.158,67.007 107.247,67.096 107.247,70.431 107.333,70.517 108.633,70.517 108.703,70.447 108.703,67.035 108.791,66.947 109.031,66.947 109.121,67.037 109.121,67.358 109.584,67.821 109.584,70.439 109.662,70.517 119.769,70.517 120.994,69.292 120.994,69.186 120.704,68.897 120.704,67.924 121.094,67.534 U29.C2@121.094,67.222
DDR_DQ15: U27.R22 U29.A3 | length 35.9
  Top Layer w0.09: U27.R22@102.4,69.6 103.232,69.6 104.44,70.807 106.441,70.807 106.661,70.587 106.661,67.682 106.743,67.599 106.876,67.599 106.957,67.68 106.957,70.705 107.059,70.807 108.94,70.807 108.993,70.754 108.993,67.867 109.046,67.814 109.167,67.814 109.294,67.941 109.294,70.754 109.346,70.807 120.01,70.807 121.286,69.532 121.286,68.986 121.495,68.776 121.495,66.99 121.709,66.776 122.34,66.776 U29.A3@122.694,66.422
DDR_DQ16: U27.D20 U28.D7 | length 52.3
  Top Layer w0.09: U27.D20@100.8,78.4 100.8,78.074 100.912,77.962 ; 100.913,77.963 101.838,77.963 101.908,77.892 103.143,77.892 103.791,78.54 103.925,78.54 104.573,77.892 104.712,77.892 105.36,78.54 106.715,78.54 107.399,77.856 107.546,77.856 108.231,78.54 138.22,78.54 141.412,75.348 141.412,74.373 ; U28.D7@137.925,70.35 137.925,70.366 138.23,70.67 138.23,72.412 138.282,72.465 141.261,72.465 141.413,72.617 141.413,72.863 141.236,73.04 141.236,73.285 141.413,73.462 141.413,73.593 141.093,73.913 141.093,74.052 141.413,74.372
DDR_DQ17: U27.C22 U28.C7 | length 50.9
  Top Layer w0.09: U27.C22@102.4,79.2 103.106,79.2 103.277,79.37 138.564,79.37 142.243,75.691 142.243,71.27 141.949,70.976 141.949,70.826 142.191,70.585 142.191,70.427 142.067,70.304 141.924,70.304 141.703,70.525 141.072,70.525 140.468,69.921 139.13,69.921 U28.C7@138.725,70.325
DDR_DQ18: U27.C21 U28.B8 | length 52.6
  Top Layer w0.09: U27.C21@101.6,79.2 101.897,79.2 102.272,79.575 102.725,79.575 102.811,79.66 138.684,79.66 142.533,75.812 142.533,70.359 142.188,70.014 141.804,70.014 141.631,70.187 141.402,70.187 141.318,70.103 141.318,69.932 141.47,69.78 141.47,69.366 141.332,69.228 140.047,69.228 139.78,69.495 139.58,69.495 U28.B8@139.525,69.55
DDR_DQ19: U27.B22 U28.C8 | length 53.2
  Top Layer w0.09: U27.B22@102.4,80 102.45,79.95 138.804,79.95 139.04,79.715 142.823,75.932 142.823,70.239 141.014,68.43 140.193,68.43 139.93,68.693 139.93,68.798 139.568,69.16 139.463,69.16 139.073,69.55 U28.C8@138.725,69.55
DDR_DQ20: U27.F20 U28.D3 | length 54.2
  Top Layer w0.09: U27.F20@100.8,76.8 101.025,76.575 103.14,76.575 103.309,76.406 105.277,76.406 105.961,77.09 106.115,77.09 106.799,76.406 108.147,76.406 108.831,77.09 109.181,77.09 109.865,76.406 110.711,76.406 111.395,77.09 111.74,77.09 112.424,76.406 113.261,76.406 113.945,77.09 114.465,77.09 115.149,76.406 115.986,76.406 116.67,77.09 116.843,77.09 117.527,76.406 118.352,76.406 119.036,77.09 119.305,77.09 119.989,76.406 120.936,76.406 121.62,77.09 122.6,77.09 122.646,77.045 122.646,76.1 123.574,75.172 124.284,75.172 124.865,75.753 124.865,76.89 125,77.025 125.225,77.025 125.376,76.875 125.376,73.68 125.721,73.335 126.42,73.335 126.7,73.615 126.7,74.601 126.925,74.825 127.6,74.825 127.755,74.98 127.755,76.67 127.881,76.796 129.196,76.796 129.49,77.09 136.46,77.09 136.545,77.005 136.545,76.795 136.3,76.55 136.3,75.9 135.95,75.55 135.95,74.96 136.15,74.761 136.786,74.761 136.852,74.695 137.323,74.695 137.47,74.548 137.47,73.897 137.818,73.55 U28.D3@137.925,73.55
DDR_DQ21: U27.F19 U28.C3 | length 54.6
  Top Layer w0.09: U27.F19@100,76.8 100.039,76.8 100.339,77.1 100.924,77.1 101.199,76.825 103.3,76.825 103.429,76.696 105.157,76.696 105.841,77.38 106.235,77.38 106.919,76.696 108.027,76.696 108.711,77.38 109.301,77.38 109.985,76.696 110.591,76.696 111.275,77.38 111.86,77.38 112.544,76.696 113.141,76.696 113.825,77.38 114.585,77.38 115.269,76.696 115.866,76.696 116.55,77.38 116.963,77.38 117.647,76.696 118.232,76.696 118.916,77.38 119.425,77.38 120.109,76.696 120.816,76.696 121.5,77.38 122.821,77.38 122.936,77.265 122.936,76.22 123.694,75.462 123.962,75.462 124.575,76.075 124.575,77.25 124.706,77.38 125.52,77.38 125.666,77.235 125.666,74.1 125.816,73.95 126.285,73.95 126.41,74.075 126.41,74.993 126.793,75.375 127.25,75.375 127.4,75.525 127.4,76.75 127.736,77.086 129.076,77.086 129.37,77.38 136.745,77.38 136.835,77.29 136.835,76.785 ; 136.835,76.765 136.835,76.24 136.98,76.095 137.289,76.095 137.52,75.864 137.52,75.848 137.527,75.842 137.527,75.644 137.528,75.642 137.528,74.983 137.537,74.974 137.537,74.964 137.768,74.733 137.778,74.733 137.781,74.73 138.161,74.73 138.325,74.566 138.325,74.188 138.712,73.801 U28.C3@138.712,73.539
DDR_DQ22: U27.E19 U28.C2 | length 54
  Top Layer w0.09: U27.E19@100,77.6 100.376,77.6 100.676,77.3 101.117,77.3 101.317,77.1 103.435,77.1 103.549,76.986 105.036,76.986 105.721,77.67 106.355,77.67 107.039,76.986 107.907,76.986 108.591,77.67 109.421,77.67 110.105,76.986 110.47,76.986 111.155,77.67 111.98,77.67 112.665,76.986 113.02,76.986 113.705,77.67 114.705,77.67 115.39,76.986 115.745,76.986 116.43,77.67 117.083,77.67 117.767,76.986 118.111,76.986 118.796,77.67 119.545,77.67 120.229,76.986 120.695,76.986 121.38,77.67 123.009,77.67 123.226,77.454 123.226,76.34 123.741,75.825 123.915,75.825 124.275,76.185 124.275,77.55 124.396,77.67 125.75,77.67 125.957,77.464 125.957,76.268 126.289,75.937 126.673,75.937 126.962,76.226 126.962,76.77 127.568,77.376 128.956,77.376 129.25,77.67 136.955,77.67 137.125,77.5 137.125,76.462 137.2,76.387 137.417,76.387 137.608,76.196 138,76.196 138.225,76.421 138.225,76.75 138.09,76.885 138.09,77.065 138.155,77.13 138.4,77.13 139.204,76.326 139.204,76.204 139.095,76.095 138.925,76.095 138.845,76.175 138.642,76.175 138.323,75.856 138.323,74.978 138.568,74.733 138.63,74.733 138.725,74.637 U28.C2@138.725,74.35
DDR_DQ23: U27.E20 U28.A3 | length 53.5
  Top Layer w0.09: U27.E20@100.8,77.6 101.1,77.6 101.4,77.3 104.94,77.3 105.601,77.96 106.475,77.96 107.159,77.276 107.787,77.276 108.471,77.96 109.541,77.96 110.225,77.276 110.35,77.276 111.035,77.96 112.1,77.96 112.785,77.276 112.9,77.276 113.585,77.96 114.825,77.96 115.51,77.276 115.625,77.276 116.31,77.96 117.203,77.96 117.887,77.276 117.991,77.276 118.676,77.96 119.665,77.96 120.349,77.276 120.575,77.276 121.26,77.96 123.164,77.96 123.516,77.608 123.516,76.46 123.778,76.198 123.878,76.198 123.95,76.27 123.95,77.725 124.186,77.96 125.99,77.96 126.247,77.703 126.247,76.798 126.35,76.695 126.592,76.695 126.672,76.775 126.672,77.499 126.839,77.666 128.836,77.666 129.13,77.96 137.115,77.96 137.425,77.65 137.425,76.788 137.494,76.719 137.719,76.719 137.8,76.8 137.8,77.3 137.92,77.42 138.52,77.42 139.625,76.315 139.625,75.862 139.137,75.374 139.137,74.086 139.278,73.945 139.905,73.945 U28.A3@140.325,73.525
DDR_DQ24: U27.G19 U28.J3 | length 42.2
  Top Layer w0.09: U27.G19@100,76 100,76.4 100.1,76.5 100.505,76.5 100.71,76.295 103.009,76.295 103.188,76.116 122.219,76.116 123.543,74.793 124.058,74.793 125.002,73.848 125.002,73.333 125.661,72.675 126.209,72.675 126.644,73.11 126.925,73.11 127,73.185 127,74.388 127.086,74.474 127.259,74.474 127.362,74.37 127.362,73.165 128.092,72.435 128.763,72.435 128.816,72.488 128.816,72.622 129.249,73.055 129.559,73.055 129.704,73.2 130.125,73.2 130.306,73.02 130.306,72.475 130.346,72.435 130.525,72.435 130.625,72.535 130.625,73.046 130.779,73.2 132.748,73.2 132.9,73.048 132.9,72.67 133.01,72.56 ; 133.011,72.56 133.14,72.56 133.358,72.778 133.77,72.778 133.925,72.933 U28.J3@133.925,73.55
DDR_DQ25: U27.G22 U28.H2 | length 39.5
  Top Layer w0.09: U27.G22@102.4,76 102.41,75.99 102.904,75.99 103.068,75.826 122.099,75.826 126.009,71.916 126.264,71.916 126.52,72.173 126.52,72.54 126.628,72.648 127.458,72.648 127.961,72.145 128.996,72.145 129.106,72.255 129.106,72.502 129.369,72.765 129.846,72.765 130.016,72.595 130.016,72.21 130.08,72.145 130.88,72.145 130.935,72.2 130.935,72.824 131.021,72.91 131.816,72.91 131.925,72.8 131.925,72.398 131.998,72.325 132.131,72.325 132.3,72.495 132.3,72.85 132.36,72.91 132.554,72.91 132.61,72.853 132.61,72.415 132.7,72.325 132.835,72.325 133.015,72.145 133.135,72.145 133.478,72.488 133.89,72.488 134.093,72.69 134.267,72.69 134.425,72.849 134.425,73.275 134.329,73.371 134.329,73.929 U28.H2@134.725,74.325
DDR_DQ26: U27.G21 U28.H3 | length 40.5
  Top Layer w0.09: U27.G21@101.6,76 101.9,76 102.2,75.7 102.784,75.7 102.948,75.536 121.969,75.536 126.424,71.08 126.678,71.08 126.81,71.213 126.81,72.251 126.918,72.358 127.338,72.358 127.841,71.855 129.287,71.855 129.396,71.964 129.396,72.382 129.489,72.475 129.601,72.475 129.726,72.35 129.726,71.951 129.822,71.855 131.03,71.855 131.225,72.05 131.225,72.39 131.319,72.483 131.55,72.483 131.627,72.407 131.627,72.008 131.78,71.855 132.165,71.855 132.345,72.035 132.715,72.035 132.895,71.855 133.255,71.855 133.598,72.198 134.011,72.198 134.213,72.4 135.008,72.4 135.135,72.526 135.135,72.715 134.725,73.124 U28.H3@134.725,73.55
DDR_DQ27: U27.G20 U28.G2 | length 41.2
  Top Layer w0.09: U27.G20@100.8,76 101.1,75.7 101.527,75.7 101.727,75.5 102.574,75.5 102.828,75.246 121.848,75.246 126.543,70.552 126.809,70.552 127.1,70.843 127.1,71.777 127.208,71.885 127.366,71.885 127.45,71.8 127.45,71.715 127.6,71.565 133.375,71.565 133.718,71.908 134.131,71.908 134.328,72.105 135.59,72.105 135.7,72.216 135.7,72.515 135.425,72.791 135.425,73.051 135.18,73.295 135.18,73.98 U28.G2@135.525,74.325
DDR_DQ28: U27.J21 U28.J7 | length 41.5
  Top Layer w0.09: U27.J21@101.6,74.4 101.614,74.4 101.892,74.122 121.368,74.122 126.35,69.14 126.635,69.14 127.45,68.325 127.45,67.229 127.779,66.9 129.995,66.9 130.152,67.057 130.152,67.502 130.4,67.75 131.301,67.75 131.63,67.421 131.63,66.997 131.728,66.9 133.223,66.9 133.566,67.243 133.858,67.243 134,67.385 134,67.525 133.8,67.725 133.6,67.725 133.505,67.82 133.505,68.86 133.768,69.123 133.898,69.123 133.98,69.205 134.068,69.205 134.303,69.439 134.303,69.973 U28.J7@133.925,70.35
DDR_DQ29: U27.J20 U28.H8 | length 41.8
  Top Layer w0.09: U27.J20@100.8,74.4 101.125,74.4 101.2,74.325 101.2,74 101.368,73.832 121.248,73.832 126.23,68.85 126.515,68.85 127.16,68.205 127.16,67.109 127.659,66.61 130.312,66.61 130.442,66.74 130.442,67.382 130.52,67.46 131.181,67.46 131.34,67.301 131.34,66.765 131.496,66.61 133.64,66.61 134.5,67.47 134.5,67.775 134.3,67.975 134.3,68.869 134.725,69.294 U28.H8@134.725,69.55
DDR_DQ30: U27.K20 U28.H7 | length 42.5
  Top Layer w0.09: U27.K20@100.8,73.6 100.858,73.542 121.128,73.542 126.11,68.56 126.395,68.56 126.87,68.085 126.87,66.988 127.539,66.32 130.432,66.32 130.732,66.62 130.732,67.028 130.8,67.096 130.998,67.096 131.05,67.043 131.05,66.584 131.314,66.32 133.795,66.32 135.1,67.625 135.1,69.692 134.725,70.067 U28.H7@134.725,70.35
DDR_DQ31: U27.L19 U28.F7 | length 42.9
  Top Layer w0.09: U27.L19@100,72.8 100.442,73.242 121.018,73.242 126.58,67.68 126.58,66.868 127.419,66.03 133.93,66.03 135.926,68.026 135.926,69.951 U28.F7@136.325,70.35
DDR_DQM0: U27.W21 U29.E7 | length 19.9
  Top Layer w0.09: U27.W21@101.6,66.4 101.921,66.721 102.694,66.721 104.982,64.434 105.459,64.434 106.16,63.732 109.138,63.732 109.706,64.3 118.416,64.3 U29.E7@119.494,63.222
DDR_DQM1: U27.P20 U29.E2 | length 36.9
  Top Layer w0.09: U27.P20@100.8,70.4 101.34,70.4 101.713,70.028 103.22,70.028 103.225,70.033 103.24,70.033 104.304,71.097 120.187,71.097 121.575,69.709 121.575,69.135 121.807,68.904 122.381,68.904 123.495,67.789 123.495,65.445 123.34,65.29 123.015,65.29 122.842,65.462 122.842,65.833 122.681,65.994 122.434,65.994 122.107,65.667 120.037,65.667 119.827,65.877 119.627,65.877 118.45,64.7 118.346,64.7 118.2,64.847 118.2,64.991 119.069,65.86 119.069,66.797 U29.E2@119.494,67.222
DDR_DQM2: U27.E21 U28.E2 | length 53.4
  Top Layer w0.09: U27.E21@101.6,77.6 103.26,77.6 103.76,78.1 103.956,78.1 104.456,77.6 104.83,77.6 105.48,78.25 106.595,78.25 107.279,77.566 107.666,77.566 108.351,78.25 138.1,78.25 141.122,75.228 141.122,74.492 140.803,74.173 140.803,73.793 141.002,73.595 141.002,73.461 140.803,73.263 140.803,72.875 140.683,72.755 140.2,72.755 140.11,72.845 140.11,73.115 139.975,73.25 139.784,73.25 139.625,73.091 139.625,72.9 139.48,72.755 138.162,72.755 137.94,72.532 137.94,71.606 137.844,71.511 137.594,71.511 137.507,71.597 137.507,72.722 137.4,72.829 136.816,72.829 136.703,72.942 136.703,73.923 137.128,74.348 U28.E2@137.125,74.35
DDR_DQM3: U27.H20 U28.E7 | length 42.1
  Top Layer w0.09: U27.H20@100.8,75.2 100.8,74.898 100.876,74.822 101.616,74.822 101.79,74.648 101.947,74.648 102.183,74.412 121.488,74.412 126.47,69.43 126.755,69.43 127.285,68.9 127.421,68.9 127.53,69.01 127.53,69.335 127.965,69.769 127.965,70.475 127.965,70.491 128.169,70.695 134.353,70.695 134.88,71.222 137.429,71.222 137.525,71.125 137.525,70.725 U28.E7@137.125,70.325
DDR_DQS0_N: U27.W20 U29.F3 | length 20.6
  Top Layer w0.09: U27.W20@100.8,66.4 101.082,66.682 101.343,66.682 101.682,67.022 102.804,67.022 105.102,64.724 105.579,64.724 106.28,64.022 109.018,64.022 109.589,64.593 117.252,64.593 118.418,65.758 118.418,66.146 U29.F3@118.694,66.422
DDR_DQS0_P: U27.V20 U29.G3 | length 20.2
  Top Layer w0.09: U27.V20@100.8,67.2 101.068,66.932 101.239,66.932 101.579,67.272 102.907,67.272 105.205,64.974 105.682,64.974 106.384,64.272 108.914,64.272 109.486,64.843 117.149,64.843 118.168,65.862 118.168,66.141 117.894,66.415 U29.G3@117.894,66.422
DDR_DQS1_N: U27.N21 U29.A7 | length 36.6
  Top Layer w0.09: U27.N21@101.6,71.2 101.6,70.904 101.936,70.568 102.996,70.568 104.066,71.637 120.411,71.637 124.035,68.013 124.035,64.911 123.586,64.462 123.069,64.462 122.455,65.076 122.244,65.076 121.783,64.614 119.904,64.614 119.8,64.511 119.8,64.352 119.896,64.257 122.056,64.257 122.41,63.903 122.41,63.506 U29.A7@122.694,63.222
DDR_DQS1_P: U27.N20 U29.B7 | length 36.9
  Top Layer w0.09: U27.N20@100.8,71.2 101.07,70.93 101.22,70.93 101.833,70.318 103.1,70.318 104.169,71.387 120.307,71.387 123.785,67.909 123.785,65.015 123.482,64.712 123.173,64.712 122.558,65.326 122.141,65.326 121.679,64.864 119.8,64.864 119.55,64.615 119.55,64.249 119.792,64.007 121.952,64.007 122.16,63.799 122.16,63.502 U29.B7@121.882,63.224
